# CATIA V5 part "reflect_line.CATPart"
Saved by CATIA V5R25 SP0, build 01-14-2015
Part number: Part1
Bounding box of the stored display mesh (mm): x -137.722 to 27.889, y -12.795 to 48.475, z 0 to 139
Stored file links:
  E:\cadcim\GSD_cat_v5-6r2014\Part_files\reflect_line.CATPart
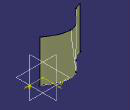
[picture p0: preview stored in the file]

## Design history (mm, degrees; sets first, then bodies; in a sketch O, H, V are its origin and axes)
Set1
  Sketch1 on xy-plane, origin (0, 0, 0), H (1, 0, 0), V (0, 1, 0)
    spline S1 through (27.8894, 17.3949) (-93.4438, 17.3949) (-113.5702, -2.4439) (-137.7218, -12.7946)
  Extrude1: Lim1 139, Lim2 0, Element1 Sketch1
  ReflectLine1: Support Extrude1, Direction (0, 0, 1), Angle 64, Origin vertex [face of Extrude1 from Sketch1.S1]
Body1 (main body)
